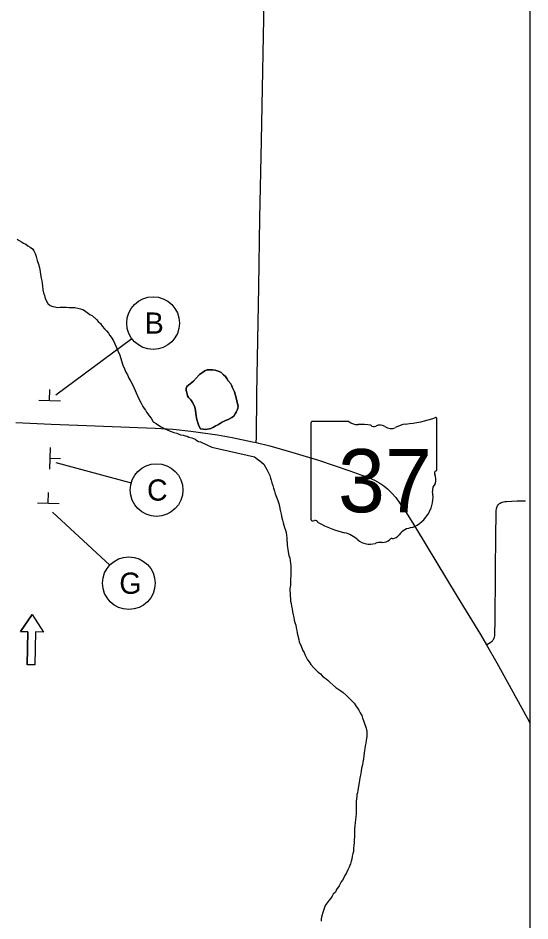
# Model space of a CAD drawing. Extents: x 1651.5 to 1685.5, y 1084.6 to 1106.6.
# Drawn here: x 1664.92 to 1668.69, y 1092.09 to 1098.72 of the extents above; entities that cross this region are included whole.
import ezdxf

# ---------------------------------------------------------------- set-up
doc = ezdxf.new("R2010")
doc.units = 0
for name, color, linetype in [('GM_X_Minor_Lake', 7, 'Continuous'), ('GM_X_Minor_River', 7, 'Continuous'), ('GM_X_State_Route', 7, 'Continuous'), ('GM_X_State_Shield', 7, 'Continuous'), ('GM_X_Township_Road', 7, 'Continuous'), ('SH_Data', 7, 'Continuous'), ('SH_Text', 7, 'Continuous'), ('SN_P_Signs', 7, 'Continuous')]:
    doc.layers.add(name, color=color, linetype=linetype)

msp = doc.modelspace()

# ---------------------------------------------------------------- linework, layer by layer
at = {"layer": 'GM_X_Minor_Lake'}
for points in [[(1666.1664, 1096.0157), (1666.2153, 1096.0525), (1666.2344, 1096.0764), (1666.2589, 1096.1029), (1666.2805, 1096.1186), (1666.2968, 1096.1291), (1666.3157, 1096.1369), (1666.3345, 1096.1367), (1666.3533, 1096.1364), (1666.3747, 1096.1335), (1666.3961, 1096.1279), (1666.4148, 1096.1196), (1666.4361, 1096.1005), (1666.4493, 1096.087), (1666.4599, 1096.0734), (1666.4704, 1096.0572), (1666.4889, 1096.0329), (1666.4968, 1096.0194), (1666.502, 1096.0059), (1666.5099, 1095.9897), (1666.5151, 1095.9763), (1666.5279, 1095.9306), (1666.533, 1095.9091), (1666.5381, 1095.8876), (1666.5433, 1095.8688), (1666.5404, 1095.8554), (1666.5348, 1095.8394), (1666.5293, 1095.8261), (1666.5211, 1095.8128), (1666.5101, 1095.7969), (1666.4966, 1095.7863), (1666.4749, 1095.7732), (1666.4453, 1095.7629), (1666.4209, 1095.7498), (1666.3992, 1095.734), (1666.3749, 1095.7236), (1666.3614, 1095.7158), (1666.3425, 1095.7053), (1666.329, 1095.7028), (1666.3021, 1095.6978), (1666.286, 1095.7007), (1666.2673, 1095.7036), (1666.2567, 1095.7198), (1666.2515, 1095.7333), (1666.2463, 1095.7468), (1666.2386, 1095.771), (1666.236, 1095.7844), (1666.2335, 1095.7978), (1666.2311, 1095.8166), (1666.2287, 1095.8381), (1666.2236, 1095.8622), (1666.2158, 1095.8838), (1666.2053, 1095.9027), (1666.1947, 1095.9162), (1666.1788, 1095.9325), (1666.1709, 1095.946), (1666.1684, 1095.9594), (1666.1607, 1095.9863), (1666.1609, 1095.9997), (1666.1664, 1096.0157)], [(1666.5101, 1095.7969), (1666.5211, 1095.8128), (1666.5293, 1095.8261), (1666.5348, 1095.8394), (1666.5404, 1095.8554), (1666.5433, 1095.8688), (1666.5381, 1095.8876), (1666.533, 1095.9091), (1666.5279, 1095.9306), (1666.5151, 1095.9763), (1666.5099, 1095.9897), (1666.502, 1096.0059), (1666.4968, 1096.0194), (1666.4889, 1096.0329), (1666.4704, 1096.0572), (1666.4599, 1096.0734), (1666.4493, 1096.087), (1666.4361, 1096.1005), (1666.4148, 1096.1196), (1666.3961, 1096.1279), (1666.3747, 1096.1335), (1666.3533, 1096.1364), (1666.3345, 1096.1367), (1666.3157, 1096.1369), (1666.2968, 1096.1291), (1666.2805, 1096.1186), (1666.2589, 1096.1029), (1666.2344, 1096.0764), (1666.2153, 1096.0525), (1666.1664, 1096.0157)], [(1666.1664, 1096.0157), (1666.1609, 1095.9997), (1666.1607, 1095.9863), (1666.1684, 1095.9594), (1666.1709, 1095.946), (1666.1788, 1095.9325), (1666.1947, 1095.9162), (1666.2053, 1095.9027), (1666.2158, 1095.8838), (1666.2236, 1095.8622), (1666.2287, 1095.8381), (1666.2311, 1095.8166), (1666.2335, 1095.7978), (1666.236, 1095.7844), (1666.2386, 1095.771), (1666.2463, 1095.7468), (1666.2515, 1095.7333), (1666.2567, 1095.7198), (1666.2673, 1095.7036), (1666.286, 1095.7007), (1666.3021, 1095.6978), (1666.329, 1095.7028), (1666.3425, 1095.7053), (1666.3614, 1095.7158), (1666.3749, 1095.7236), (1666.3992, 1095.734), (1666.4209, 1095.7498), (1666.4453, 1095.7629), (1666.4749, 1095.7732), (1666.4966, 1095.7863), (1666.5101, 1095.7969)]]:
    msp.add_lwpolyline(points, dxfattribs=at)
at = {"layer": 'GM_X_Minor_River'}
for points in [[(1664.9179, 1097.0982), (1664.9338, 1097.0872), (1664.9499, 1097.079), (1664.9658, 1097.0681), (1664.9819, 1097.0598), (1664.9978, 1097.0489), (1665.0138, 1097.038), (1665.0298, 1097.027), (1665.0403, 1097.0108), (1665.0508, 1096.9919), (1665.0586, 1096.9704), (1665.0663, 1096.9408), (1665.074, 1096.914), (1665.0817, 1096.8871), (1665.0868, 1096.8602), (1665.0892, 1096.8388), (1665.0942, 1096.8119), (1665.0993, 1096.7904), (1665.1017, 1096.7716), (1665.1042, 1096.7555), (1665.1065, 1096.726)], [(1665.1065, 1096.726), (1665.1116, 1096.7019), (1665.1194, 1096.683), (1665.1245, 1096.6615), (1665.1429, 1096.6238), (1665.1615, 1096.6101), (1665.1802, 1096.6018), (1665.1963, 1096.5989), (1665.2123, 1096.5961), (1665.2338, 1096.5985), (1665.25, 1096.5982), (1665.2661, 1096.598), (1665.2822, 1096.5978), (1665.2983, 1096.5949), (1665.3117, 1096.5948), (1665.3278, 1096.5945), (1665.3412, 1096.5944), (1665.3653, 1096.5914), (1665.3841, 1096.5858), (1665.4001, 1096.5802), (1665.4134, 1096.572), (1665.4321, 1096.5584), (1665.4534, 1096.5447), (1665.472, 1096.5337), (1665.5012, 1096.5066), (1665.5145, 1096.493), (1665.5304, 1096.4767), (1665.5436, 1096.4578), (1665.5595, 1096.4388), (1665.5754, 1096.4225), (1665.5886, 1096.4063), (1665.5991, 1096.3901), (1665.6097, 1096.3766), (1665.6255, 1096.3496), (1665.636, 1096.328), (1665.6464, 1096.3064), (1665.6595, 1096.2768), (1665.6725, 1096.2445), (1665.6854, 1096.2041), (1665.6958, 1096.1719), (1665.7062, 1096.1449), (1665.7166, 1096.1207), (1665.7297, 1096.0991), (1665.7402, 1096.0748), (1665.7533, 1096.0506), (1665.7665, 1096.029), (1665.8135, 1095.9239), (1665.8292, 1095.8915), (1665.8423, 1095.8672), (1665.8529, 1095.8537), (1665.8608, 1095.8402), (1665.8687, 1095.8267), (1665.8792, 1095.8132), (1665.8898, 1095.7997), (1665.903, 1095.7807), (1665.9188, 1095.7537), (1665.9401, 1095.7427), (1665.9641, 1095.7263), (1665.9774, 1095.7181), (1665.9907, 1095.7099), (1666.0094, 1095.7017), (1666.0281, 1095.6934), (1666.0441, 1095.6851), (1666.0575, 1095.6823), (1666.0709, 1095.6767), (1666.0923, 1095.6711), (1666.119, 1095.66), (1666.1378, 1095.6571), (1666.1538, 1095.6515), (1666.1672, 1095.6487), (1666.1806, 1095.6432), (1666.202, 1095.6375), (1666.226, 1095.6265), (1666.2393, 1095.6183), (1666.2526, 1095.6101), (1666.266, 1095.6072), (1666.3504, 1095.568)], [(1666.3504, 1095.568), (1666.6639, 1095.4974), (1666.6852, 1095.4813), (1666.7012, 1095.4679), (1666.7306, 1095.4437), (1666.7439, 1095.4222), (1666.7546, 1095.4035), (1666.7653, 1095.3794), (1666.7759, 1095.3606), (1666.7812, 1095.3419), (1666.7865, 1095.3258), (1666.7918, 1095.307), (1666.7971, 1095.2856), (1666.8025, 1095.2669), (1666.8104, 1095.2454), (1666.8157, 1095.2267), (1666.8237, 1095.1999), (1666.8344, 1095.1758), (1666.8423, 1095.1544), (1666.8476, 1095.1329), (1666.8529, 1095.1062), (1666.8582, 1095.0767), (1666.8635, 1095.05), (1666.8688, 1095.0312), (1666.8741, 1095.0125), (1666.8794, 1094.9964), (1666.8847, 1094.9777), (1666.89, 1094.9589), (1666.8954, 1094.9402), (1666.898, 1094.9214), (1666.9006, 1094.9027), (1666.9006, 1094.884), (1666.9032, 1094.8625), (1666.9032, 1094.8492), (1666.9058, 1094.8331), (1666.9084, 1094.8144), (1666.9111, 1094.801), (1666.9137, 1094.7849), (1666.9164, 1094.7715), (1666.9217, 1094.7555), (1666.9243, 1094.7367), (1666.9269, 1094.7126), (1666.9296, 1094.6966), (1666.9295, 1094.6511), (1666.9294, 1094.6377), (1666.9294, 1094.6217), (1666.9267, 1094.5976), (1666.9266, 1094.5789), (1666.9266, 1094.5548), (1666.9265, 1094.5414), (1666.9238, 1094.5281), (1666.9238, 1094.512), (1666.9264, 1094.4959), (1666.9264, 1094.4745), (1666.929, 1094.4558), (1666.929, 1094.4371), (1666.9316, 1094.4183), (1666.9343, 1094.3996), (1666.9396, 1094.3808), (1666.9422, 1094.3594), (1666.9475, 1094.3353), (1666.9528, 1094.3166), (1666.9554, 1094.2979), (1666.9607, 1094.2791), (1666.966, 1094.2604), (1666.9687, 1094.2416), (1666.974, 1094.2202), (1666.9766, 1094.2015), (1666.9819, 1094.1854), (1666.9846, 1094.172), (1666.9899, 1094.1559), (1666.9925, 1094.1345), (1667.0032, 1094.1131), (1667.0085, 1094.0997), (1667.0138, 1094.0863), (1667.0191, 1094.0729), (1667.0271, 1094.0595), (1667.0324, 1094.0434), (1667.0458, 1094.0193), (1667.0537, 1094.0059), (1667.0644, 1093.9898), (1667.0778, 1093.971), (1667.0991, 1093.9469), (1667.1151, 1093.9308), (1667.1311, 1093.9147), (1667.1472, 1093.9013), (1667.1605, 1093.8878), (1667.1765, 1093.8744), (1667.1899, 1093.8663), (1667.2033, 1093.8556), (1667.2166, 1093.8422), (1667.262, 1093.8019), (1667.2834, 1093.7885), (1667.2967, 1093.7777), (1667.3154, 1093.7643), (1667.3395, 1093.7428), (1667.3608, 1093.7213), (1667.3795, 1093.7052), (1667.3955, 1093.6864), (1667.4089, 1093.6677), (1667.4195, 1093.6489)], [(1667.4195, 1093.6489), (1667.4302, 1093.6355), (1667.4409, 1093.6167), (1667.4515, 1093.5953), (1667.4568, 1093.5765), (1667.4648, 1093.5605), (1667.4701, 1093.5444), (1667.4754, 1093.531), (1667.4781, 1093.5176), (1667.4834, 1093.5042), (1667.4887, 1093.4775), (1667.4887, 1093.4614), (1667.4886, 1093.4427), (1667.4859, 1093.4293), (1667.4832, 1093.4132), (1667.4805, 1093.3919), (1667.4778, 1093.3731), (1667.475, 1093.3544), (1667.4723, 1093.3384), (1667.4696, 1093.3223), (1667.4669, 1093.3009), (1667.4641, 1093.2769), (1667.4587, 1093.2528), (1667.456, 1093.2341), (1667.4506, 1093.21), (1667.4479, 1093.1859), (1667.4425, 1093.1565), (1667.4371, 1093.1378), (1667.4344, 1093.1191), (1667.4316, 1093.1031), (1667.4235, 1093.0469), (1667.4208, 1093.0282), (1667.4154, 1093.0148), (1667.4153, 1093.0014), (1667.4126, 1092.9827), (1667.4099, 1092.9667), (1667.4099, 1092.9373), (1667.4098, 1092.9158), (1667.4097, 1092.8918), (1667.4097, 1092.873), (1667.407, 1092.849), (1667.4069, 1092.8302), (1667.4042, 1092.8089), (1667.4015, 1092.7848), (1667.3988, 1092.7634), (1667.3987, 1092.7286), (1667.3986, 1092.7045), (1667.3959, 1092.6831), (1667.3958, 1092.6617), (1667.3931, 1092.6403), (1667.3904, 1092.6216), (1667.3903, 1092.5975), (1667.385, 1092.5815), (1667.3822, 1092.5628), (1667.3795, 1092.5414), (1667.3741, 1092.5253), (1667.3687, 1092.5066), (1667.358, 1092.4826), (1667.3499, 1092.4612), (1667.3391, 1092.4398), (1667.3284, 1092.4211), (1667.3203, 1092.4024), (1667.3096, 1092.3864), (1667.3015, 1092.3731), (1667.2935, 1092.3597), (1667.2854, 1092.3437), (1667.2666, 1092.317), (1667.2585, 1092.2983), (1667.2425, 1092.2823), (1667.2344, 1092.2689), (1667.2236, 1092.2529), (1667.2129, 1092.2396), (1667.1968, 1092.2182), (1667.1834, 1092.1995), (1667.1645, 1092.1488), (1667.1591, 1092.1247), (1667.1537, 1092.1007), (1667.1537, 1092.0846)]]:
    msp.add_lwpolyline(points, dxfattribs=at)
at = {"layer": 'GM_X_State_Route'}
for points in [[(1664.9073, 1095.7491), (1665.1676, 1095.737), (1665.3646, 1095.7309), (1665.9334, 1095.7091), (1666.0647, 1095.6999), (1666.1955, 1095.6854), (1666.3908, 1095.6584), (1666.499, 1095.6403), (1666.6492, 1095.6085), (1666.6766, 1095.6018)], [(1666.6766, 1095.6018), (1666.7769, 1095.5772), (1666.9459, 1095.5304), (1667.1343, 1095.4721), (1667.363, 1095.3957), (1667.4457, 1095.3657), (1667.5006, 1095.3448), (1667.5452, 1095.3248), (1667.5842, 1095.3047), (1667.6143, 1095.2846), (1667.64, 1095.2635), (1667.6735, 1095.2312), (1667.7013, 1095.1977), (1667.7292, 1095.1598), (1667.7779, 1095.0892), (1667.8479, 1094.9775), (1668.1541, 1094.472), (1668.3243, 1094.191), (1668.3696, 1094.1145), (1668.4457, 1093.9829), (1668.6677, 1093.5802), (1668.6882, 1093.5432)]]:
    msp.add_lwpolyline(points, dxfattribs=at)
at = {"layer": 'GM_X_State_Shield'}
for p, q in [((1668.0048, 1095.4059), (1668.0048, 1095.7744)), ((1667.0767, 1095.7448), (1667.0767, 1095.0404)), ((1667.3576, 1095.7569), (1667.0858, 1095.7569)), ((1668.0047, 1095.406), (1668.0048, 1095.4059))]:
    msp.add_line(p, q, dxfattribs=at)
for centre, radius, start, end in [((1667.6742, 1096.7173), 0.9842, 275.84447, 288.90645), ((1667.9945, 1095.7759), 0.0103, 351.86209, 97.738), ((1667.0873, 1095.7463), 0.0108, 98.1301, 188.1301), ((1667.4223, 1095.8387), 0.1043, 231.61951, 271.11188), ((1667.4569, 1095.3615), 0.3744, 80.48669, 94.98827), ((1667.5419, 1095.75), 0.0301, 219.79206, 297.10237), ((1667.5861, 1095.6685), 0.0626, 54.46668, 119.14113), ((1667.6668, 1095.7802), 0.0753, 233.85621, 294.82819), ((1667.7997, 1095.5418), 0.198, 97.34618, 120.76885), ((1668.0024, 1095.3788), 0.016, 107.94398, 210.33697), ((1667.9006, 1095.3323), 0.096, 340.03296, 23.64957), ((1667.9937, 1095.4045), 0.0111, 289.60381, 7.73413), ((1668.0418, 1095.2517), 0.0698, 136.8065, 186.92959), ((1667.7293, 1095.2048), 0.2462, 292.30889, 8.98584), ((1667.0874, 1095.0388), 0.0108, 171.95839, 258.30661), ((1667.089, 1095.1109), 0.0828, 267.33899, 280.60386), ((1667.106, 1094.9997), 0.0298, 29.74838, 93.27175), ((1667.4828, 1095.6326), 0.7108, 240.41292, 257.1985), ((1667.8331, 1094.8426), 0.1348, 94.40312, 142.57675), ((1667.2709, 1094.7239), 0.2224, 47.18416, 75.83597), ((1667.6623, 1094.9721), 0.0795, 282.87319, 323.27711), ((1667.5114, 1094.9963), 0.1411, 230.70037, 286.29184), ((1667.593, 1094.7527), 0.116, 85.69512, 111.20995), ((1667.6033, 1094.9435), 0.0752, 268.77702, 315.54927), ((1667.6713, 1094.8753), 0.0212, 65.75173, 132.64842)]:
    msp.add_arc(centre, radius, start, end, dxfattribs=at)
at = {"layer": 'GM_X_Township_Road'}
for points in [[(1666.6766, 1095.6018), (1666.677, 1095.6384), (1666.6809, 1095.9598), (1666.6942, 1096.7478), (1666.7029, 1097.2512), (1666.7142, 1097.8203), (1666.7356, 1098.9803), (1666.7384, 1099.243), (1666.7435, 1099.5056), (1666.7533, 1100.206), (1666.7573, 1100.3592), (1666.7567, 1100.4293)], [(1668.3696, 1094.1145), (1668.3894, 1094.1268), (1668.4008, 1094.1347), (1668.4063, 1094.1394), (1668.4127, 1094.1459), (1668.4157, 1094.1495), (1668.4203, 1094.1559), (1668.423, 1094.1605), (1668.4257, 1094.167), (1668.4275, 1094.1728), (1668.4291, 1094.1807), (1668.4304, 1094.1914), (1668.4312, 1094.2042), (1668.4312, 1094.2194), (1668.4326, 1094.2688), (1668.4326, 1094.2939), (1668.4331, 1094.3872), (1668.4348, 1094.544), (1668.435, 1094.6665), (1668.4371, 1094.9115), (1668.4398, 1095.0865), (1668.4403, 1095.0992), (1668.4406, 1095.1039), (1668.4415, 1095.1121), (1668.4425, 1095.1176), (1668.4447, 1095.1261), (1668.4466, 1095.1314), (1668.4494, 1095.137), (1668.4543, 1095.1441), (1668.4599, 1095.1497), (1668.4646, 1095.1538), (1668.4702, 1095.1575), (1668.4768, 1095.1609), (1668.4849, 1095.1638), (1668.4933, 1095.166), (1668.5032, 1095.1681), (1668.5149, 1095.1692), (1668.5937, 1095.173), (1668.6551, 1095.1752)]]:
    msp.add_lwpolyline(points, dxfattribs=at)
at = {"layer": 'SH_Data'}
msp.add_lwpolyline([(1653.9882, 1105.4005), (1668.6882, 1105.4005), (1668.6882, 1085.8005), (1653.9882, 1085.8005)], close=True, dxfattribs=at)
at = {"layer": 'SH_Text'}
for p, q in [((1665.2033, 1095.9521), (1665.7608, 1096.3668)), ((1665.2036, 1095.4549), (1665.7568, 1095.3061)), ((1665.1773, 1095.0897), (1665.5985, 1094.7015)), ((1665.0291, 1094.3384), (1664.9416, 1094.2128)), ((1665.0291, 1094.3384), (1665.1112, 1094.2092)), ((1664.9416, 1094.2128), (1664.9962, 1094.2116)), ((1664.9962, 1094.2116), (1664.9911, 1093.9696)), ((1665.0542, 1094.2104), (1665.0491, 1093.9684)), ((1665.1112, 1094.2092), (1665.0542, 1094.2104)), ((1665.0491, 1093.9684), (1664.9911, 1093.9696))]:
    msp.add_line(p, q, dxfattribs=at)
msp.add_lwpolyline([(1664.9911, 1093.9696), (1664.9962, 1094.2116), (1664.9416, 1094.2128), (1665.0291, 1094.3384), (1665.1112, 1094.2092), (1665.0542, 1094.2104), (1665.0491, 1093.9684)], close=True, dxfattribs=at)
for centre in [(1665.9175, 1096.4806), (1665.9432, 1095.2536), (1665.7394, 1094.5687)]:
    msp.add_circle(centre, 0.1936, dxfattribs=at)
at = {"layer": 'SN_P_Signs'}
for p, q in [((1665.1564, 1095.912), (1665.1585, 1095.992)), ((1665.0764, 1095.9141), (1665.2364, 1095.9099)), ((1665.1604, 1095.5671), (1665.1555, 1095.4072)), ((1665.158, 1095.4871), (1665.2379, 1095.4847)), ((1665.1466, 1095.1564), (1665.1487, 1095.2363)), ((1665.0666, 1095.1585), (1665.2266, 1095.1543))]:
    msp.add_line(p, q, dxfattribs=at)

# ---------------------------------------------------------------- texts
at = {"layer": 'GM_X_State_Shield'}
msp.add_text('37', height=0.46406, dxfattribs=at).set_placement((1667.2769, 1095.0901))
at = {"layer": 'SH_Text'}
for s, p in [('B', (1665.8567, 1096.4026)), ('C', (1665.8732, 1095.1756)), ('G', (1665.6694, 1094.4907))]:
    msp.add_text(s, height=0.156, dxfattribs=at).set_placement(p)

doc.saveas('drawing.dxf')
